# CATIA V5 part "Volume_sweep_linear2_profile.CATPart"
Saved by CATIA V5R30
Part number: Part1
Bounding box of the stored display mesh (mm): x -59.804 to 154.398, y 1.869 to 39.866, z 0 to 157
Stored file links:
  D:\PROJECTS\CATIA V56R 2020\Resources\Parts File\c17_catia_v6_6r2020_prt\Volume_sweep_linear2_profile.CATPart
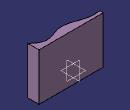
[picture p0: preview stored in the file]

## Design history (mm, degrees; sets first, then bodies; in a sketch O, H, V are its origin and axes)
Set1
  Sketch1 on xy-plane, origin (0, 0, 0), H (1, 0, 0), V (0, 1, 0)
    spline S1 through (154.3979, 1.8689) (93.1563, 21.7077) (57.7914, 10.782) (13.5134, 17.6824) (-59.804, 28.3207)
  Extrude1: Element1 Sketch1, Lim1 157, Lim2 0
  Sweep1: type Segment, GuideCrv Extrude1, Length1 10, Length2 0, Angle 0, DraftDirection zx-plane
Body1 (main body)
